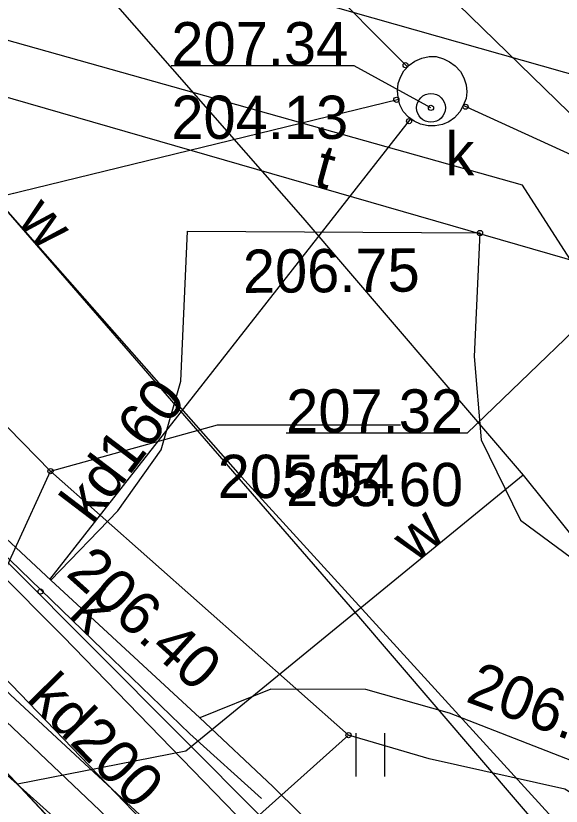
# Model space of a CAD drawing. Extents: x 6512606 to 6513006, y 6022524 to 6022728.
# Drawn here: x 6512819.16 to 6512828.62, y 6022654.83 to 6022668.54 of the extents above; entities that cross this region are included whole.
import ezdxf

# ---------------------------------------------------------------- set-up
doc = ezdxf.new("R2010")
doc.units = 0
for name, color, linetype in [('216-obręb ewidencyjny', 7, 'Continuous'), ('218-kontur użytku gruntowego', 7, 'Continuous'), ('219-działka ewidencyjna', 7, 'Continuous'), ('312-budynek ewidencyjny', 7, 'Continuous'), ('4', 7, 'Continuous'), ('905-Brama w ogrodzeniu', 7, 'Continuous'), ('940-Trawnik symb. poj.', 7, 'Continuous'), ('chodnik (powierzchnia)', 7, 'Continuous'), ('Default', 7, 'Continuous'), ('inna obudowa przewodu - sieć kanalizacyjna (linia)', 7, 'Continuous'), ('inna obudowa przewodu - sieć kanalizacyjna (linia)-Atr1', 7, 'Continuous'), ('inna obudowa przewodu - sieć telekomunikacyjna (linia)', 7, 'Continuous'), ('komora podziemna - przewód kanalizacyjny (powierzchnia)', 7, 'Continuous'), ('przewód elektroenergetyczny (linia)', 7, 'Continuous'), ('przewód gazowy (linia)', 7, 'Continuous'), ('przewód kanalizacyjny (linia)', 7, 'Continuous'), ('przewód kanalizacyjny (linia)-Atr1', 7, 'Continuous'), ('przewód telekomunikacyjny (linia)', 7, 'Continuous'), ('przewód telekomunikacyjny (linia)-Atr1', 7, 'Continuous'), ('przewód wodociągowy (linia)', 7, 'Continuous'), ('przewód wodociągowy (linia)-Atr1', 7, 'Continuous'), ('punkt o określonej wysokości (sieć gazowa)', 7, 'Continuous'), ('punkt o określonej wysokości (sieć gazowa)-Atr2', 7, 'Continuous'), ('punkt o określonej wysokości (sieć gazowa)-Atr3', 7, 'Continuous'), ('punkt o określonej wysokości (sieć kanalizacyjna)', 7, 'Continuous'), ('punkt o określonej wysokości (sieć kanalizacyjna)-Atr2', 7, 'Continuous'), ('punkt o określonej wysokości (sieć kanalizacyjna)-Atr3', 7, 'Continuous'), ('punkt o określonej wysokości (sieć telekomunikacyjna)-Atr2', 7, 'Continuous'), ('punkt o określonej wysokości (sieć telekomunikacyjna)-Atr3', 7, 'Continuous'), ('punkt wysokościowy sztuczny', 7, 'Continuous'), ('punkt wysokościowy sztuczny-Atr2', 7, 'Continuous'), ('rura ochronna - przewód gazowy (linia)', 7, 'Continuous'), ('właz okrągły - siec kanalizacyjna (punkt)', 7, 'Continuous'), ('właz okrągły - siec kanalizacyjna (punkt)-Atr17', 7, 'Continuous')]:
    doc.layers.add(name, color=color, linetype=linetype)

# ---------------------------------------------------------------- blocks, each defined once
blk = doc.blocks.new('PW01')
at = {"layer": 'Default'}
blk.add_circle((0, 0), 0.45, dxfattribs=at)
blk = doc.blocks.new('PW02')
at = {"layer": 'Default'}
blk.add_circle((0, 0), 0.45, dxfattribs=at)
blk = doc.blocks.new('905')
at = {"layer": 'Default'}
for centre, start, end in [((-15, 0), 0, 60), ((15, 0), 120, 180)]:
    blk.add_arc(centre, 15, start, end, dxfattribs=at)
blk = doc.blocks.new('940P')
at = {"layer": 'Default'}
for p, q in [((-2.5, -3.75), (-2.5, 3.75)), ((2.5, -3.75), (2.5, 3.75))]:
    blk.add_line(p, q, dxfattribs=at)
blk = doc.blocks.new('US22')
at = {"layer": 'Default'}
blk.add_circle((0, 0), 2.5, dxfattribs=at)

msp = doc.modelspace()

# ---------------------------------------------------------------- linework, layer by layer
at = {"layer": '216-obręb ewidencyjny'}
for points in [[(6512836.687, 6022675.173), (6512833.61, 6022675.02), (6512828.67, 6022670.98), (6512801.96, 6022670.34), (6512810.18, 6022663.28), (6512825.37, 6022649.66), (6512838.47, 6022634.29), (6512852.25, 6022608.25), (6512853.17, 6022604.51), (6512855.78, 6022583.95), (6512858.85, 6022571.74), (6512828.23, 6022562.62), (6512818.47, 6022559.72), (6512824.714, 6022553.406)], [(6512852.25, 6022608.25), (6512838.47, 6022634.29), (6512825.37, 6022649.66), (6512810.18, 6022663.28), (6512801.96, 6022670.34), (6512796.96, 6022674.74), (6512790.49, 6022674.74), (6512785.56, 6022674.74), (6512768.24, 6022674.27), (6512754.87, 6022673.72), (6512745.51, 6022673.33), (6512735.76, 6022672.94), (6512730.35, 6022672.71), (6512725.78, 6022672.95), (6512702.575, 6022674.177)]]:
    msp.add_lwpolyline(points, dxfattribs=at)
at = {"layer": '218-kontur użytku gruntowego'}
for points in [[(6512825.37, 6022649.66), (6512810.18, 6022663.28)], [(6512810.18, 6022663.28), (6512825.37, 6022649.66)]]:
    msp.add_lwpolyline(points, dxfattribs=at)
at = {"layer": '219-działka ewidencyjna'}
msp.add_lwpolyline([(6512825.37, 6022649.66), (6512810.18, 6022663.28)], dxfattribs=at)
at = {"layer": '312-budynek ewidencyjny'}
msp.add_lwpolyline([(6512816.1, 6022658.5), (6512824.72, 6022649.31)], dxfattribs=at)
at = {"layer": '4'}
msp.add_lwpolyline([(6512825.37, 6022649.66), (6512810.18, 6022663.28)], dxfattribs=at)
at = {"layer": 'chodnik (powierzchnia)'}
for points in [[(6512845.61, 6022610.5), (6512844.69, 6022613.44), (6512844.06, 6022613.28), (6512843.41, 6022615.01), (6512844.01, 6022615.23), (6512838.87, 6022629.83), (6512839.52, 6022630.32), (6512838.94, 6022631.84), (6512838.15, 6022631.88), (6512837.86, 6022632.79), (6512838.13, 6022633.96), (6512826.89, 6022646.81), (6512825.11, 6022648.85), (6512824.32, 6022649.76), (6512820.29, 6022654.03), (6512817.62, 6022656.88), (6512816.1, 6022658.5), (6512810.3, 6022663.44), (6512802.06, 6022670.47), (6512797.05, 6022674.74)], [(6512830.64, 6022661.41), (6512827.95, 6022665.6), (6512807.24, 6022671.43), (6512806.47, 6022670.54), (6512810.75, 6022666.84), (6512818.47, 6022659.95), (6512819.77, 6022658.75), (6512822.35, 6022656.36), (6512823.62, 6022655.17), (6512828.35, 6022650.49), (6512830.32, 6022651.26)], [(6512830.51, 6022654.95), (6512826.68, 6022656.44), (6512825.23, 6022656.85), (6512823.58, 6022656.86), (6512822.35, 6022656.36), (6512819.77, 6022658.75), (6512820.93, 6022659.95), (6512821.68, 6022661.01), (6512822.02, 6022662.2), (6512822.14, 6022664.8), (6512827.21, 6022664.77), (6512827.11, 6022662.63), (6512827.23, 6022661.18), (6512827.91, 6022659.79), (6512829.17, 6022658.86)]]:
    msp.add_lwpolyline(points, dxfattribs=at)
msp.add_lwpolyline([(6512812.21, 6022672.23), (6512829.02, 6022667.46), (6512831.23, 6022666.85), (6512832.78, 6022666.53), (6512833.94, 6022666.42), (6512838.17, 6022666.38), (6512837.9, 6022666.78), (6512836.24, 6022668.51), (6512834.25, 6022670.06), (6512832.02, 6022671.17), (6512829.48, 6022671.98), (6512827.66, 6022672.22), (6512821.17, 6022672.6), (6512812.18, 6022673.12)], close=True, dxfattribs=at)
at = {"layer": 'inna obudowa przewodu - sieć kanalizacyjna (linia)'}
msp.add_lwpolyline([(6512818.34, 6022659.79), (6512820.67, 6022657.54), (6512822.18, 6022656.08), (6512823.42, 6022654.96)], dxfattribs=at)
at = {"layer": 'inna obudowa przewodu - sieć telekomunikacyjna (linia)'}
msp.add_lwpolyline([(6512829.04, 6022664.23), (6512828.99, 6022664.24), (6512804.11, 6022671.43), (6512804.07, 6022671.44)], dxfattribs=at)
at = {"layer": 'komora podziemna - przewód kanalizacyjny (powierzchnia)'}
msp.add_lwpolyline([(6512826.98, 6022667.22), (6512826.97, 6022667.1), (6512826.92, 6022666.98), (6512826.86, 6022666.87), (6512826.77, 6022666.77), (6512826.67, 6022666.7), (6512826.56, 6022666.65), (6512826.43, 6022666.63), (6512826.31, 6022666.63), (6512826.18, 6022666.66), (6512826.07, 6022666.71), (6512825.97, 6022666.78), (6512825.88, 6022666.88), (6512825.82, 6022666.99), (6512825.79, 6022667.12), (6512825.78, 6022667.24), (6512825.79, 6022667.36), (6512825.83, 6022667.47), (6512825.89, 6022667.58), (6512825.98, 6022667.68), (6512826.08, 6022667.75), (6512826.2, 6022667.8), (6512826.33, 6022667.83), (6512826.45, 6022667.83), (6512826.58, 6022667.79), (6512826.68, 6022667.74), (6512826.78, 6022667.67), (6512826.87, 6022667.57), (6512826.93, 6022667.46), (6512826.97, 6022667.34)], close=True, dxfattribs=at)
at = {"layer": 'przewód elektroenergetyczny (linia)'}
for points in [[(6512702.569, 6022673.878), (6512710.28, 6022673.25), (6512716.66, 6022675.97), (6512746.13, 6022674.3), (6512752.79, 6022674.32), (6512760.61, 6022675.35), (6512763.38, 6022676.06), (6512798.79, 6022676.04), (6512803.06, 6022673.02), (6512807.84, 6022668.96), (6512815.24, 6022662.53), (6512819.98, 6022657.77), (6512831.6, 6022645.79), (6512834.59, 6022642.25), (6512837.06, 6022638.75), (6512840.02, 6022634.13), (6512842.26, 6022630.04), (6512846.03, 6022621.35), (6512846.58, 6022618.9), (6512847.6, 6022616.23), (6512852.12, 6022605.09)], [(6512802.27, 6022673.66), (6512807.42, 6022670.09), (6512811.38, 6022666.87), (6512814.66, 6022663.43), (6512826.4, 6022651.65), (6512827.82, 6022650.09), (6512834.03, 6022642.46), (6512842.84, 6022631.19), (6512844.67, 6022626.95), (6512847.57, 6022619.87), (6512849.81, 6022612.67), (6512853.56, 6022600.08), (6512856.46, 6022588.83), (6512861.26, 6022569.82), (6512861.768, 6022567.654)], [(6512832.38, 6022663.33), (6512825.55, 6022669.99), (6512821.54, 6022670.81), (6512817.88, 6022671.15)]]:
    msp.add_lwpolyline(points, dxfattribs=at)
at = {"layer": 'przewód gazowy (linia)'}
for points in [[(6512819.76, 6022660.64), (6512816.09, 6022664.39)], [(6512817.9, 6022656.58), (6512819.76, 6022660.64)], [(6512847.18, 6022613.76), (6512846.63, 6022615.41), (6512849.08, 6022617.22), (6512845.94, 6022626.61), (6512846.16, 6022628.38), (6512844.18, 6022631.79), (6512844.23, 6022632.26), (6512844.43, 6022634.25), (6512844.47, 6022634.75), (6512844, 6022635.91), (6512842.48, 6022639.61), (6512842.1, 6022640.54), (6512841.83, 6022641.94), (6512833.52, 6022652.16), (6512828.68, 6022655.12), (6512826.33, 6022655.65), (6512824.93, 6022656.06), (6512819.76, 6022660.64)]]:
    msp.add_lwpolyline(points, dxfattribs=at)
at = {"layer": 'przewód kanalizacyjny (linia)'}
for points in [[(6512825.95, 6022667.65), (6512808.46, 6022685.21)], [(6512809.75, 6022675.66), (6512823.01, 6022660.61), (6512831.4, 6022651.41), (6512840.81, 6022640.51)], [(6512812.44, 6022663.83), (6512825.8, 6022667.09)], [(6512835.32, 6022663.14), (6512826.92, 6022666.98)], [(6512819.75, 6022658.76), (6512826.01, 6022666.75)], [(6512825.42, 6022650.35), (6512812.44, 6022663.83)]]:
    msp.add_lwpolyline(points, dxfattribs=at)
at = {"layer": 'przewód telekomunikacyjny (linia)'}
for points in [[(6512829.92, 6022664.12), (6512829.04, 6022664.23), (6512828.99, 6022664.24), (6512804.11, 6022671.43), (6512803.2, 6022671.69)], [(6512803.2, 6022671.69), (6512803.68, 6022670.87), (6512814.12, 6022660.92), (6512820.62, 6022654.75), (6512822.04, 6022653.36), (6512827.37, 6022648.58), (6512829.25, 6022646.9)], [(6512829.25, 6022646.9), (6512828.69, 6022647.83), (6512819.07, 6022656.76), (6512812.33, 6022663.22), (6512803.2, 6022671.69)]]:
    msp.add_lwpolyline(points, dxfattribs=at)
at = {"layer": 'przewód wodociągowy (linia)'}
for points in [[(6512809.35, 6022681.88), (6512813.75, 6022676.76), (6512817.99, 6022672.04), (6512824.14, 6022665.03), (6512827.96, 6022660.57), (6512832.92, 6022654.39), (6512839.85, 6022645.35)], [(6512829.45, 6022652.92), (6512828.62, 6022654.02), (6512825.04, 6022658.2), (6512818.12, 6022666.17), (6512815.22, 6022667.12)], [(6512827.96, 6022660.57), (6512822.11, 6022655.78), (6512819.19, 6022655.21)]]:
    msp.add_lwpolyline(points, dxfattribs=at)
at = {"layer": 'punkt o określonej wysokości (sieć gazowa)-Atr2'}
for points in [[(6512819.76, 6022660.64), (6512822.66, 6022661.44), (6512825.833, 6022661.44)], [(6512824.93, 6022656.06), (6512821.57, 6022653.05), (6512818.397, 6022653.05)]]:
    msp.add_lwpolyline(points, dxfattribs=at)
at = {"layer": 'punkt o określonej wysokości (sieć kanalizacyjna)-Atr2'}
msp.add_lwpolyline([(6512826.36, 6022666.94), (6512825.03, 6022667.67), (6512821.857, 6022667.67)], dxfattribs=at)
at = {"layer": 'punkt o określonej wysokości (sieć telekomunikacyjna)-Atr2'}
msp.add_lwpolyline([(6512829.92, 6022664.12), (6512826.99, 6022661.3), (6512823.849, 6022661.3)], dxfattribs=at)
at = {"layer": 'rura ochronna - przewód gazowy (linia)'}
msp.add_lwpolyline([(6512828.68, 6022655.12), (6512826.33, 6022655.65)], dxfattribs=at)

# ---------------------------------------------------------------- block references
at = {"layer": '905-Brama w ogrodzeniu', "xscale": 0.1, "yscale": 0.10000000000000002, "rotation": 133.939}
msp.add_blockref('905', (6512818.88, 6022655.54), dxfattribs=at)
at = {"layer": '940-Trawnik symb. poj.', "xscale": 0.1, "yscale": 0.10000000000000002}
msp.add_blockref('940P', (6512825.31, 6022655.72), dxfattribs=at)
at = {"layer": 'punkt o określonej wysokości (sieć gazowa)', "xscale": 0.1, "yscale": 0.10000000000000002}
for p in [(6512819.76, 6022660.64), (6512824.93, 6022656.06)]:
    msp.add_blockref('PW01', p, dxfattribs=at)
at = {"layer": 'punkt o określonej wysokości (sieć kanalizacyjna)', "xscale": 0.1}
for p, yscale, rotation in [((6512825.92, 6022667.68), 0.09999999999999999, -44.297000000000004), ((6512825.76, 6022667.08), 0.09999999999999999, 14.491), ((6512826.96, 6022666.96), 0.09999999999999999, -23.761000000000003), ((6512825.98, 6022666.71), 0.10000000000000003, 52.724)]:
    msp.add_blockref('PW01', p, dxfattribs=dict(at, yscale=yscale, rotation=rotation))
at = {"layer": 'punkt o określonej wysokości (sieć kanalizacyjna)', "xscale": 0.1, "yscale": 0.10000000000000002}
msp.add_blockref('PW01', (6512826.36, 6022666.94), dxfattribs=at)
at = {"layer": 'punkt wysokościowy sztuczny', "xscale": 0.1, "yscale": 0.10000000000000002}
for p in [(6512827.21, 6022664.77), (6512819.59, 6022658.55)]:
    msp.add_blockref('PW02', p, dxfattribs=at)
at = {"layer": 'właz okrągły - siec kanalizacyjna (punkt)', "xscale": 0.1, "yscale": 0.10000000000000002}
msp.add_blockref('US22', (6512826.36, 6022666.94), dxfattribs=at)

# ---------------------------------------------------------------- texts
at = {"layer": 'inna obudowa przewodu - sieć kanalizacyjna (linia)-Atr1'}
msp.add_text('k', height=0.75, rotation=316.001, dxfattribs=at).set_placement((6512820.06, 6022658.13))
at = {"layer": 'przewód kanalizacyjny (linia)-Atr1'}
for s, rotation, p in [('kd160', 52.745, (6512820.48, 6022659.7)), ('kd200', 314.719, (6512819.33, 6022656.68))]:
    msp.add_text(s, height=0.75, rotation=rotation, dxfattribs=at).set_placement(p)
at = {"layer": 'przewód telekomunikacyjny (linia)-Atr1'}
msp.add_text('t', height=0.75, rotation=344.685, dxfattribs=at).set_placement((6512824.3, 6022665.6))
at = {"layer": 'przewód wodociągowy (linia)-Atr1'}
for rotation, p in [(311.763, (6512819.17, 6022664.98)), (40.468, (6512826.09, 6022659.03))]:
    msp.add_text('w', height=0.75, rotation=rotation, dxfattribs=at).set_placement(p)
at = {"layer": 'punkt o określonej wysokości (sieć gazowa)-Atr3'}
msp.add_text('205.54', height=0.75, dxfattribs=at).set_placement((6512822.66, 6022660.173))
at = {"layer": 'punkt o określonej wysokości (sieć kanalizacyjna)-Atr2'}
msp.add_text('207.34', height=0.75, dxfattribs=at).set_placement((6512821.857, 6022667.678))
at = {"layer": 'punkt o określonej wysokości (sieć kanalizacyjna)-Atr3'}
msp.add_text('204.13', height=0.75, dxfattribs=at).set_placement((6512821.857, 6022666.402))
at = {"layer": 'punkt o określonej wysokości (sieć telekomunikacyjna)-Atr2'}
msp.add_text('207.32', height=0.75, dxfattribs=at).set_placement((6512823.849, 6022661.308))
at = {"layer": 'punkt o określonej wysokości (sieć telekomunikacyjna)-Atr3'}
msp.add_text('205.60', height=0.75, dxfattribs=at).set_placement((6512823.849, 6022660.032))
at = {"layer": 'punkt wysokościowy sztuczny-Atr2'}
for s, rotation, p in [('206.75', 0.452, (6512823.1, 6022663.73)), ('206.40', 318, (6512820.01, 6022658.84)), ('206.92', 339.493, (6512826.94, 6022656.65))]:
    msp.add_text(s, height=0.75, rotation=rotation, dxfattribs=at).set_placement(p)
at = {"layer": 'właz okrągły - siec kanalizacyjna (punkt)-Atr17'}
msp.add_text('k', height=0.75, dxfattribs=at).set_placement((6512826.61, 6022665.77))

doc.saveas('drawing.dxf')
